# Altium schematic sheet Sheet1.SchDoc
size E
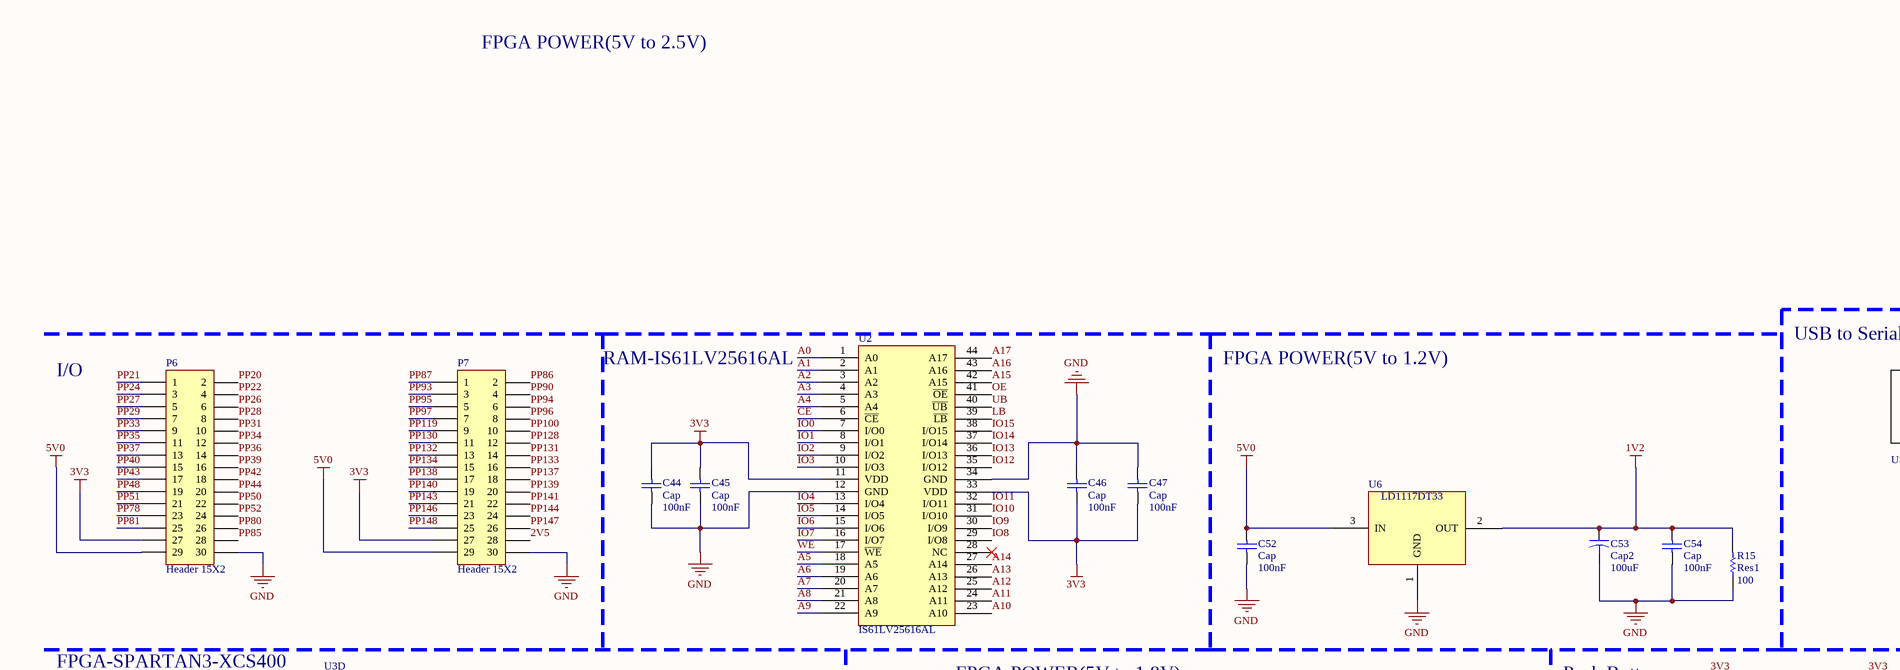
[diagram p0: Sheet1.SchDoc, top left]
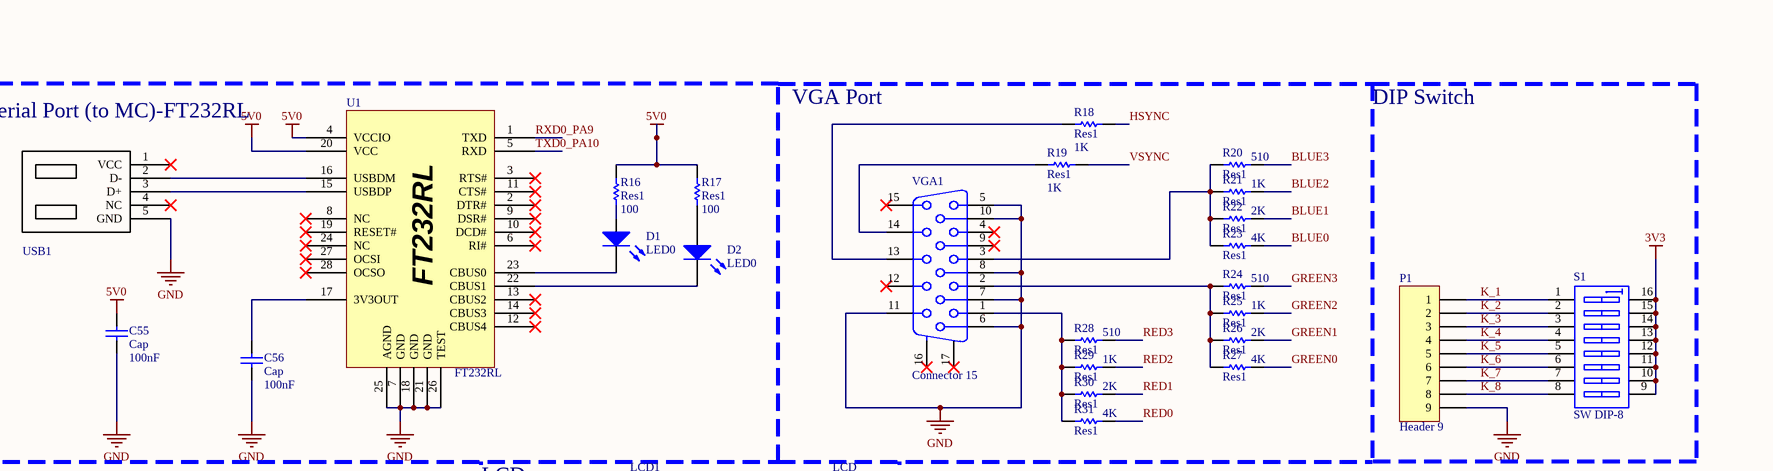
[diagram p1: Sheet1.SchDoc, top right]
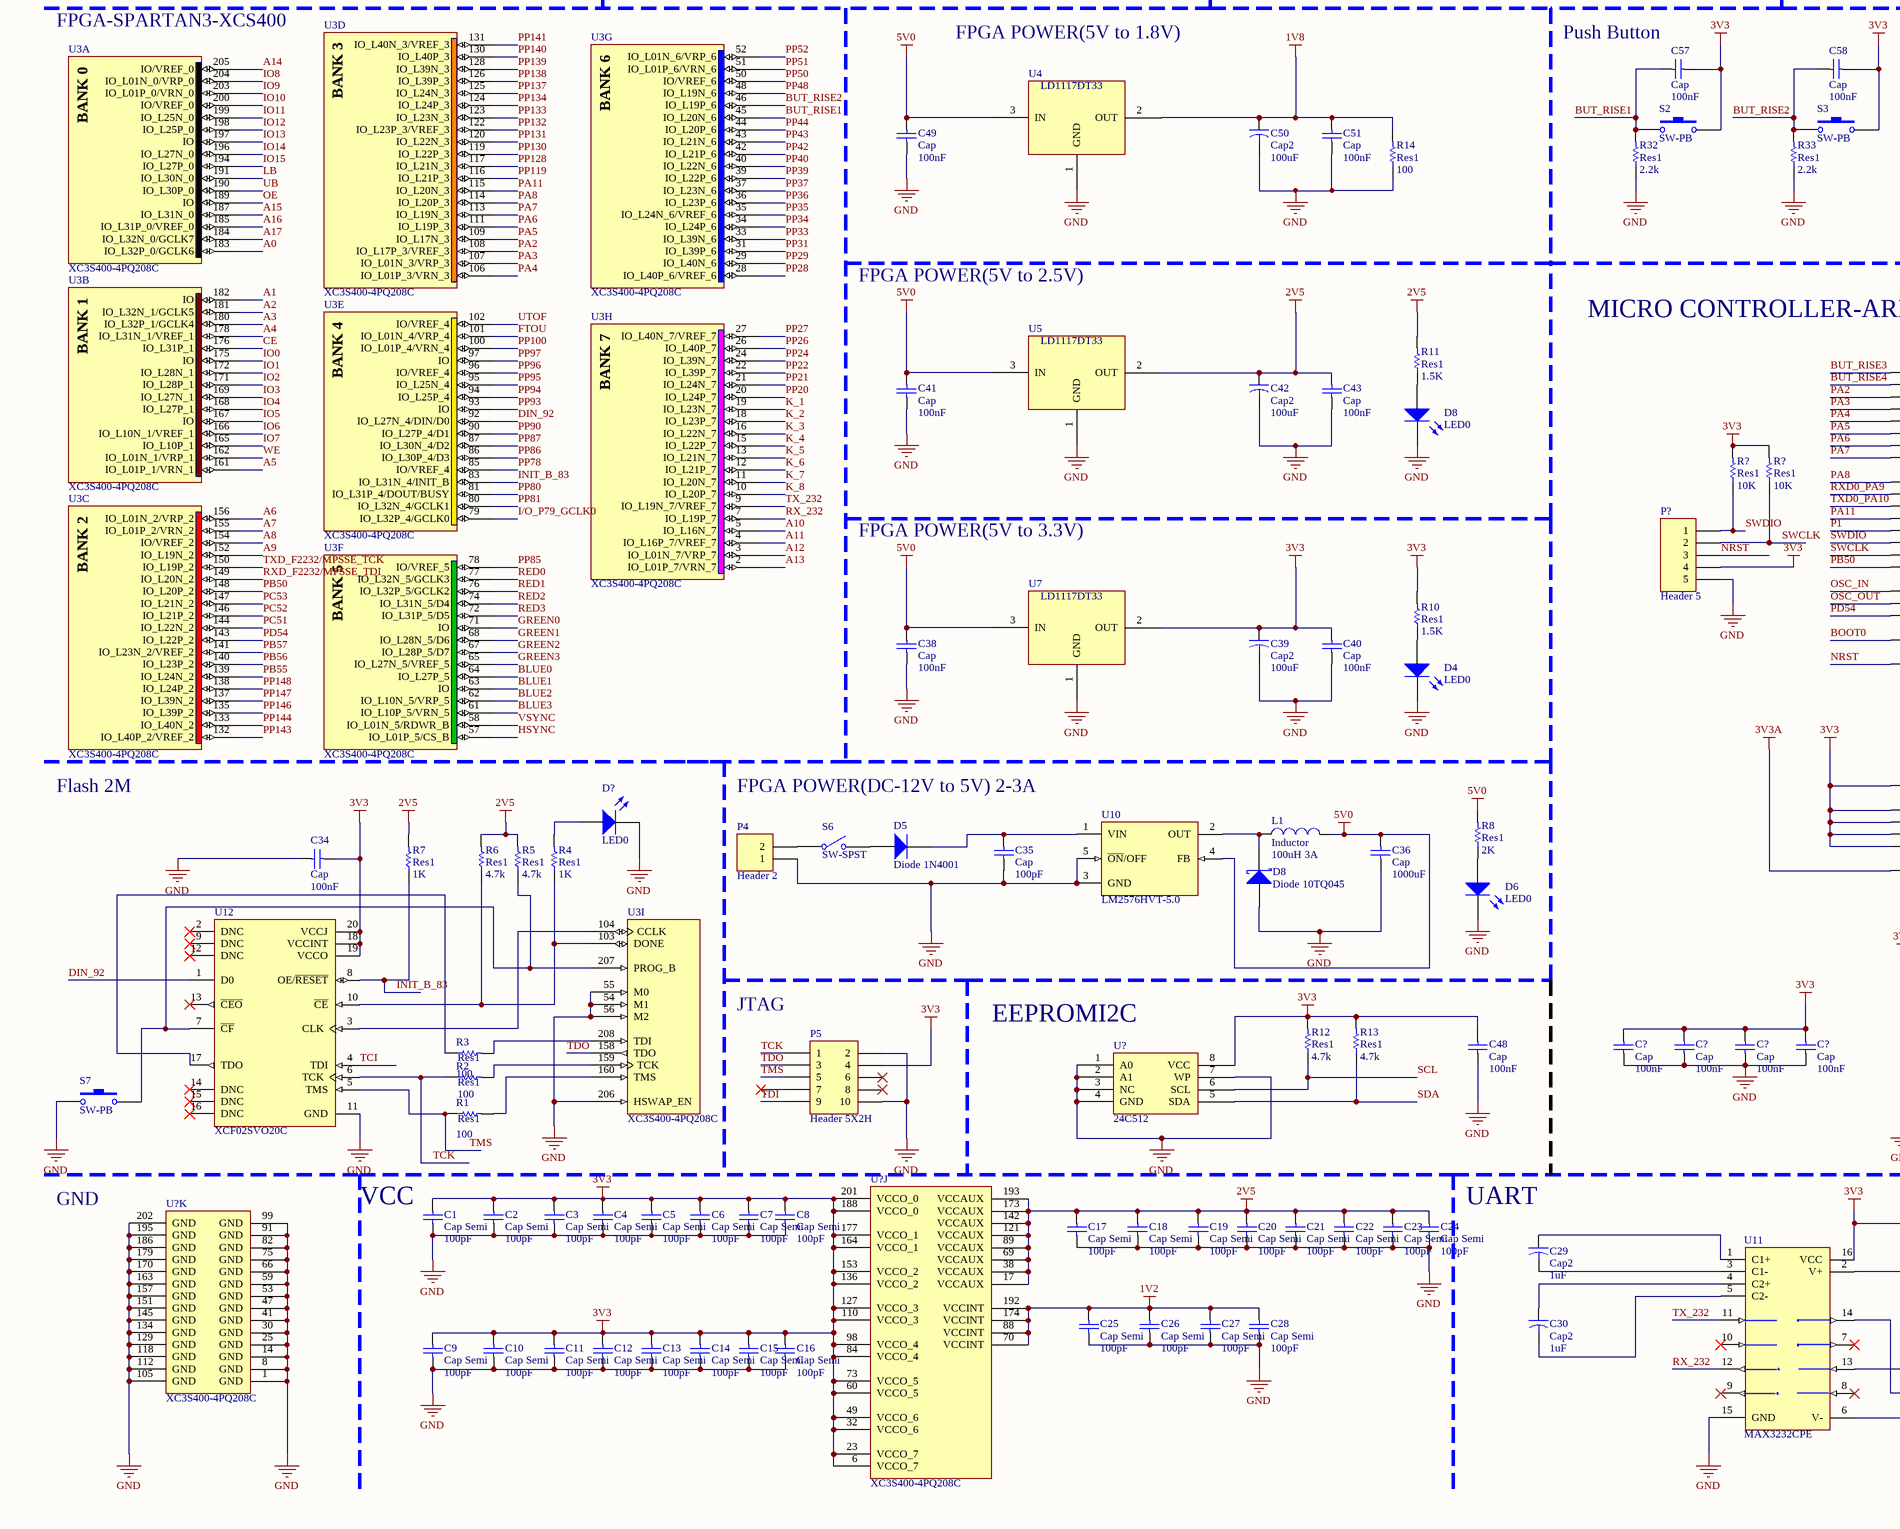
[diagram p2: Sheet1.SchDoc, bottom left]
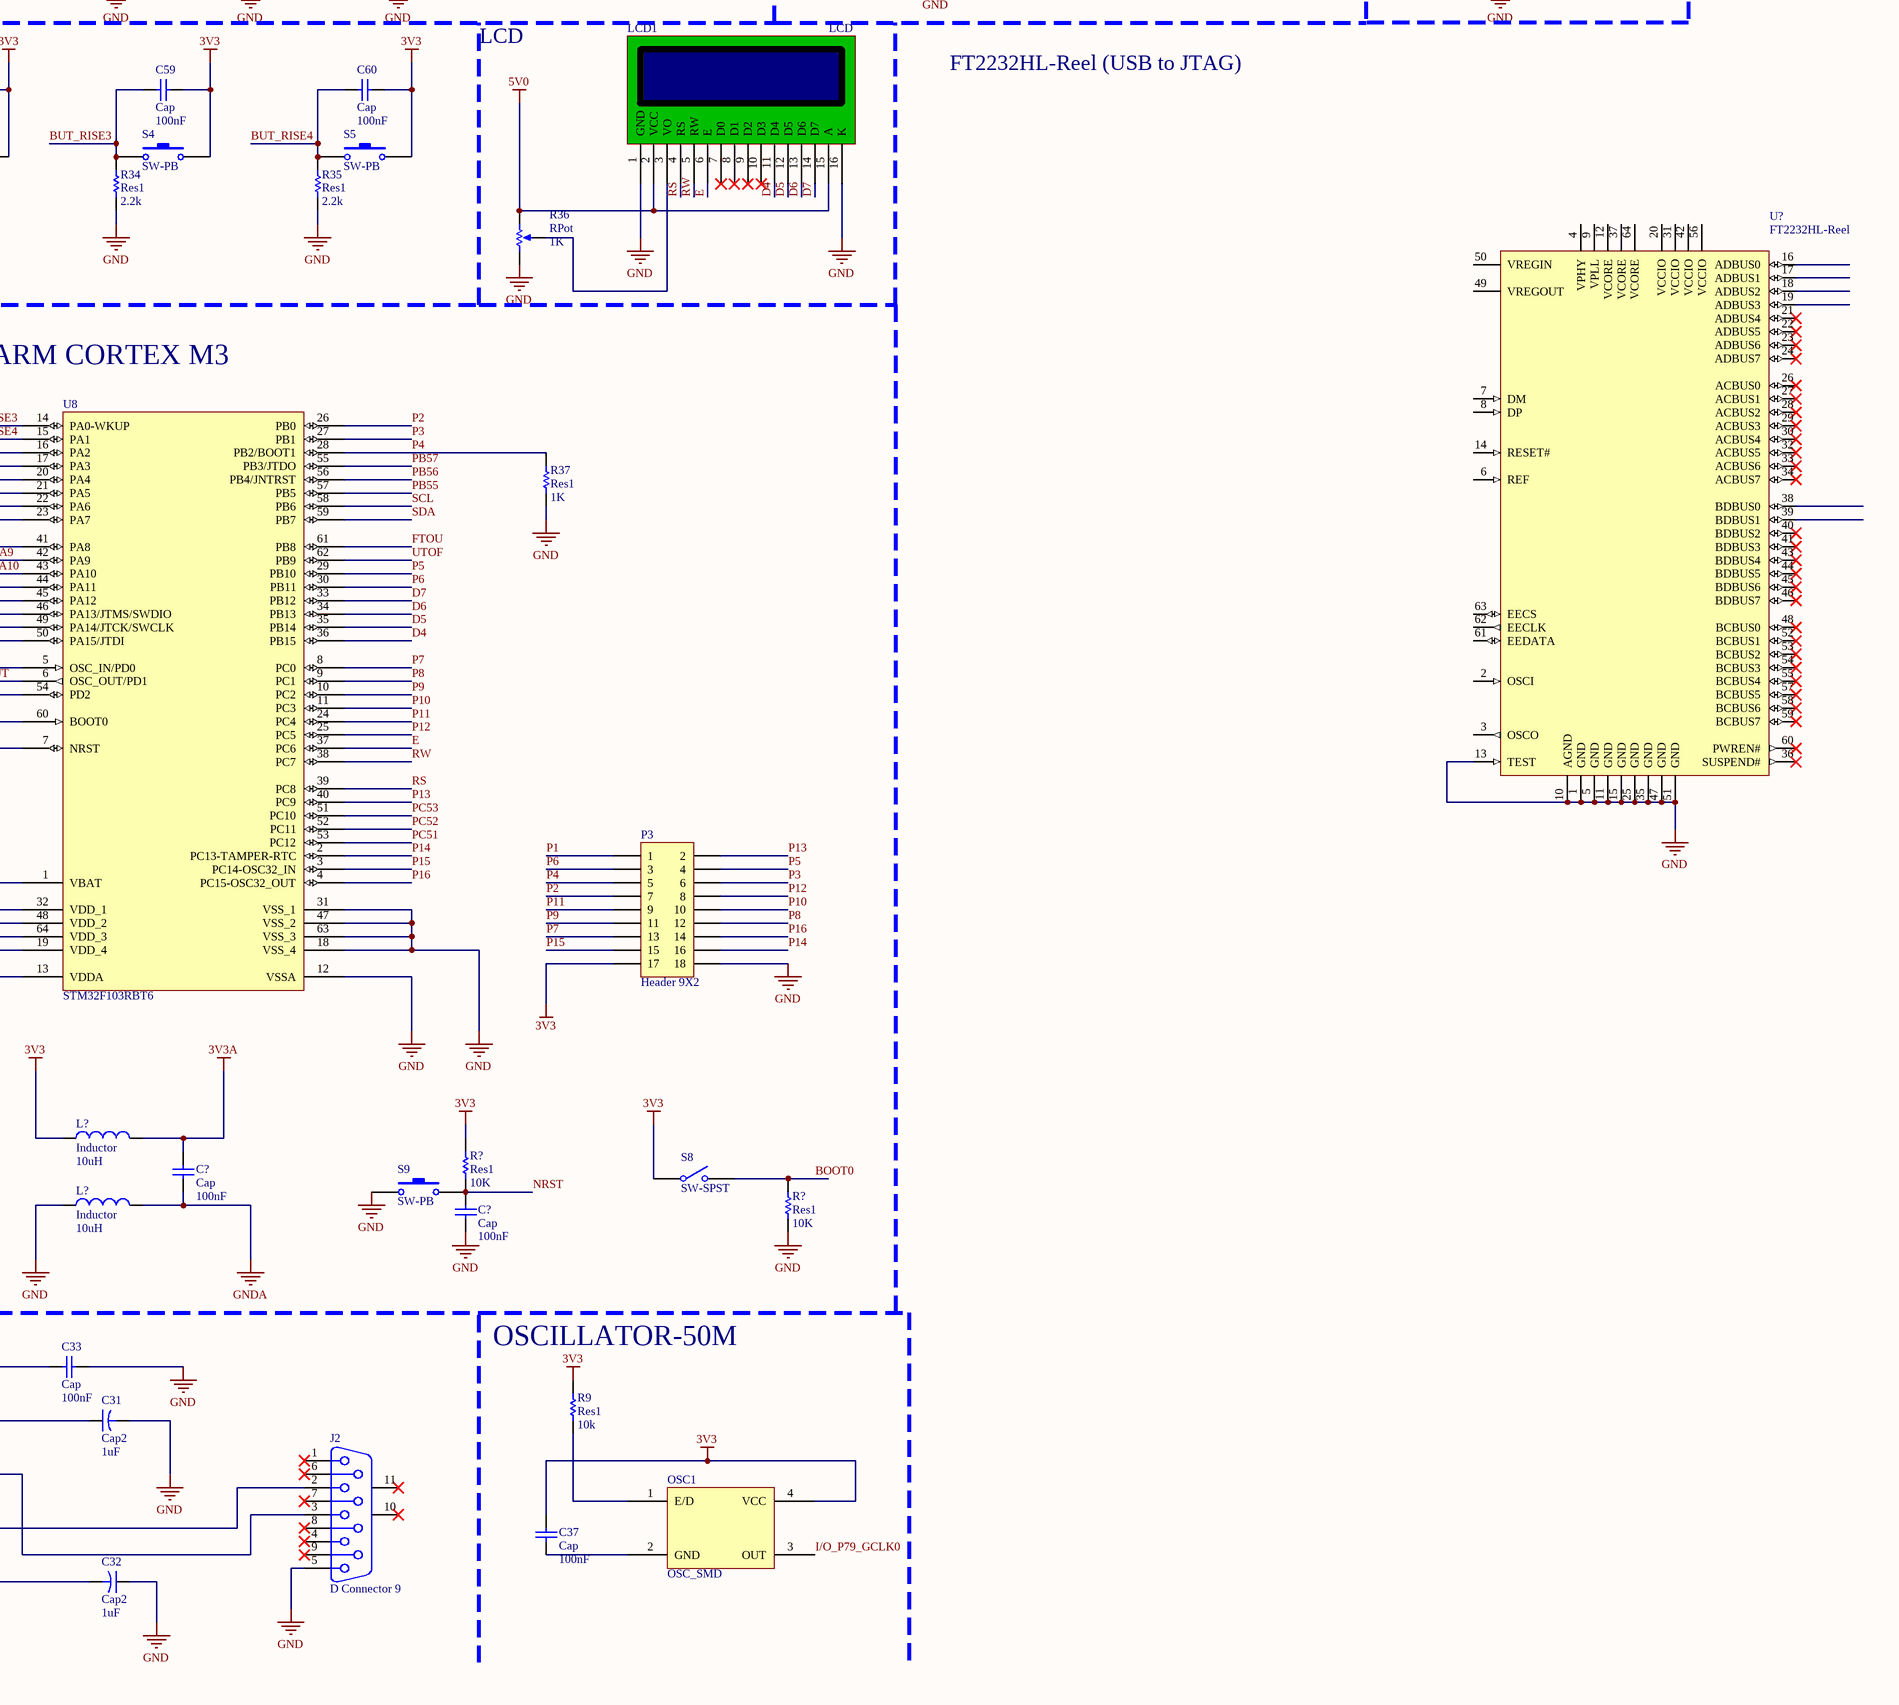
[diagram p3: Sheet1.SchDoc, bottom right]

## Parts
(Parts that share a designator on the sheet are numbered #1, #2 ... from top to bottom, then left to right.)
C1  Cap Semi  value 100pF  [C1206]
C2  Cap Semi  value 100pF  [C1206]
C3  Cap Semi  value 100pF  [C1206]
C4  Cap Semi  value 100pF  [C1206]
C5  Cap Semi  value 100pF  [C1206]
C6  Cap Semi  value 100pF  [C1206]
C7  Cap Semi  value 100pF  [C1206]
C8  Cap Semi  value 100pF  [C1206]
C9  Cap Semi  value 100pF  [C1206]
C10  Cap Semi  value 100pF  [C1206]
C11  Cap Semi  value 100pF  [C1206]
C12  Cap Semi  value 100pF  [C1206]
C13  Cap Semi  value 100pF  [C1206]
C14  Cap Semi  value 100pF  [C1206]
C15  Cap Semi  value 100pF  [C1206]
C16  Cap Semi  value 100pF  [C1206]
C17  Cap Semi  value 100pF  [C1206]
C18  Cap Semi  value 100pF  [C1206]
C19  Cap Semi  value 100pF  [C1206]
C20  Cap Semi  value 100pF  [C1206]
C21  Cap Semi  value 100pF  [C1206]
C22  Cap Semi  value 100pF  [C1206]
C23  Cap Semi  value 100pF  [C1206]
C24  Cap Semi  value 100pF  [C1206]
C25  Cap Semi  value 100pF  [C1206]
C26  Cap Semi  value 100pF  [C1206]
C27  Cap Semi  value 100pF  [C1206]
C28  Cap Semi  value 100pF  [C1206]
C29  Cap2  value 1uF  [CAPR5-4X5]
C30  Cap2  value 1uF  [CAPR5-4X5]
C31  Cap2  value 1uF  [CAPR5-4X5]
C32  Cap2  value 1uF  [CAPR5-4X5]
C33  Cap  value 100nF  [RAD-0.3]
C34  Cap  value 100nF  [RAD-0.3]
C35  Cap  value 100pF  [RAD-0.3]
C36  Cap  value 1000uF  [RAD-0.3]
C37  Cap  value 100nF  [RAD-0.3]
C38  Cap  value 100nF  [RAD-0.3]
C39  Cap2  value 100uF  [CAPR5-4X5]
C40  Cap  value 100nF  [RAD-0.3]
C41  Cap  value 100nF  [RAD-0.3]
C42  Cap2  value 100uF  [CAPR5-4X5]
C43  Cap  value 100nF  [RAD-0.3]
C44  Cap  value 100nF  [RAD-0.3]
C45  Cap  value 100nF  [RAD-0.3]
C46  Cap  value 100nF  [RAD-0.3]
C47  Cap  value 100nF  [RAD-0.3]
C48  Cap  value 100nF  [RAD-0.3]
C49  Cap  value 100nF  [RAD-0.3]
C50  Cap2  value 100uF  [CAPR5-4X5]
C51  Cap  value 100nF  [RAD-0.3]
C52  Cap  value 100nF  [RAD-0.3]
C53  Cap2  value 100uF  [CAPR5-4X5]
C54  Cap  value 100nF  [RAD-0.3]
C55  Cap  value 100nF  [RAD-0.3]
C56  Cap  value 100nF  [RAD-0.3]
C57  Cap  value 100nF  [RAD-0.3]
C58  Cap  value 100nF  [RAD-0.3]
C59  Cap  value 100nF  [RAD-0.3]
C60  Cap  value 100nF  [RAD-0.3]
C?#1  Cap  value 100nF  [RAD-0.3]
C?#2  Cap  value 100nF  [RAD-0.3]
C?#3  Cap  value 100nF  [RAD-0.3]
C?#4  Cap  value 100nF  [RAD-0.3]
C?#5  Cap  value 100nF  [RAD-0.3]
C?#6  Cap  value 100nF  [RAD-0.3]
D1  LED0  [LED-0]
D2  LED0  [LED-0]
D4  LED0  [LED-0]
D5  Diode 1N4001  [DO-41]
D6  LED0  [LED-0]
D8#1  LED0  [LED-0]
D8#2  Diode 10TQ045  [TO-220AC]
D?  LED0  [LED-0]
J2  D Connector 9  [DSUB1.385-2H9]
L1  Inductor  value 100uH 3A  [0402-A]
L?#1  Inductor  value 10uH  [0402-A]
L?#2  Inductor  value 10uH  [0402-A]
LCD1  LCD  [LCD2x16_3d]
OSC1  OSC_SMD  [OSC_SMD]
P1  Header 9  [HDR1X9]
P3  Header 9X2  [HDR2X9]
P4  Header 2  [HDR1X2]
P5  Header 5X2H  [HDR2X5H]
P6  Header 15X2  [HDR2X15]
P7  Header 15X2  [HDR2X15]
P?  Header 5  [HDR1X5]
R1  Res1  value 100  [AXIAL-0.3]
R2  Res1  value 100  [AXIAL-0.3]
R3  Res1  value 100  [AXIAL-0.3]
R4  Res1  value 1K  [AXIAL-0.3]
R5  Res1  value 4.7k  [AXIAL-0.3]
R6  Res1  value 4.7k  [AXIAL-0.3]
R7  Res1  value 1K  [AXIAL-0.3]
R8  Res1  value 2K  [AXIAL-0.3]
R9  Res1  value 10k  [AXIAL-0.3]
R10  Res1  value 1.5K  [AXIAL-0.3]
R11  Res1  value 1.5K  [AXIAL-0.3]
R12  Res1  value 4.7k  [AXIAL-0.3]
R13  Res1  value 4.7k  [AXIAL-0.3]
R14  Res1  value 100  [AXIAL-0.3]
R15  Res1  value 100  [AXIAL-0.3]
R16  Res1  value 100  [AXIAL-0.3]
R17  Res1  value 100  [AXIAL-0.3]
R18  Res1  value 1K  [AXIAL-0.3]
R19  Res1  value 1K  [AXIAL-0.3]
R20  Res1  value 510  [AXIAL-0.3]
R21  Res1  value 1K  [AXIAL-0.3]
R22  Res1  value 2K  [AXIAL-0.3]
R23  Res1  value 4K  [AXIAL-0.3]
R24  Res1  value 510  [AXIAL-0.3]
R25  Res1  value 1K  [AXIAL-0.3]
R26  Res1  value 2K  [AXIAL-0.3]
R27  Res1  value 4K  [AXIAL-0.3]
R28  Res1  value 510  [AXIAL-0.3]
R29  Res1  value 1K  [AXIAL-0.3]
R30  Res1  value 2K  [AXIAL-0.3]
R31  Res1  value 4K  [AXIAL-0.3]
R32  Res1  value 2.2k  [AXIAL-0.3]
R33  Res1  value 2.2k  [AXIAL-0.3]
R34  Res1  value 2.2k  [AXIAL-0.3]
R35  Res1  value 2.2k  [AXIAL-0.3]
R36  RPot  value 1K  [VR5]
R37  Res1  value 1K  [AXIAL-0.3]
R?#1  Res1  value 10K  [AXIAL-0.3]
R?#2  Res1  value 10K  [AXIAL-0.3]
R?#3  Res1  value 10K  [AXIAL-0.3]
R?#4  Res1  value 10K  [AXIAL-0.3]
S1  SW DIP-8  [DIP_SW_8WAY_SMD]
S2  SW-PB  [SPST-2]
S3  SW-PB  [SPST-2]
S4  SW-PB  [SPST-2]
S5  SW-PB  [SPST-2]
S6  SW-SPST  [SPST-2]
S7  SW-PB  [SPST-2]
S8  SW-SPST  [SPST-2]
S9  SW-PB  [SPST-2]
U1  FT232RL  [SOP28]
U2  IS61LV25616AL  [SOP44]
U3  XC3S400-4PQ208C  [PQ208_N]  (parts A,B,C,D,E,F,G,H,I of 11)
U4  LD1117DT33  [SOT223]
U5  LD1117DT33  [SOT223]
U6  LD1117DT33  [SOT223]
U7  LD1117DT33  [SOT223]
U8  STM32F103RBT6  [LQFP64_N]
U10  LM2576HVT-5.0  [T05A]
U11  MAX3232CPE  [PE16]
U12  XCF02SVO20C  [VO20_N]
U?#1  FT2232HL-Reel  [PCBComponent_1]
U?#2  24C512  [SOP8]
U?#3  XC3S400-4PQ208C  [PQ208_N]  (part J of 11)
U?#4  XC3S400-4PQ208C  [PQ208_N]  (part K of 11)
USB1  MICRO_USB  [MINI_USB_NEW]  (value not drawn)
VGA1  Connector 15  [050DSUB0.762-4H15]

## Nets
1V2: C25.2 C26.2 C27.2 C28.2 C53.1 C54.2 R15.2 U6.2(OUT) U?#3.70(VCCINT) U?#3.88(VCCINT) U?#3.174(VCCINT) U?#3.192(VCCINT)
1V8: C50.1 C51.2 R14.2 U4.2(OUT)
2V5: C17.2 C18.2 C19.2 C20.2 C21.2 C22.2 C23.2 C24.2 C42.1 C43.2 P7.28 R5.2 R6.2 R7.2 R11.2 U5.2(OUT) U?#3.17(VCCAUX) U?#3.38(VCCAUX) U?#3.69(VCCAUX) U?#3.89(VCCAUX) U?#3.121(VCCAUX) U?#3.142(VCCAUX) U?#3.173(VCCAUX) U?#3.193(VCCAUX)
3V3: C1.2 C2.2 C3.2 C4.2 C5.2 C6.2 C7.2 C8.2 C9.2 C10.2 C11.2 C12.2 C13.2 C14.2 C15.2 C16.2 C33.1 C34.2 C37.2 C39.1 C40.2 C44.2 C45.2 C46.1 C47.1 C48.2 C57.2 C58.2 C59.2 C60.2 C?#1.2 C?#2.2 C?#3.2 C?#4.2 L?#1.1 OSC1.4(VCC) P3.17 P5.4 P6.27 P7.27 P?.4 R9.2 R10.2 R12.2 R13.2 R?#1.2 R?#2.2 R?#3.2 S1.9(B8) S1.10(B7) S1.11(B6) S1.12(B5) S1.13(B4) S1.14(B3) S1.15(B2) S1.16(B1) S2.2 S3.2 S4.2 S5.2 S8.1(COMMON) U2.11(VDD) U2.33(VDD) U7.2(OUT) U8.1(VBAT) U8.19(VDD_4) U8.32(VDD_1) U8.48(VDD_2) U8.64(VDD_3) U11.16(VCC) U12.18(VCCINT) U12.19(VCCO) U12.20(VCCJ) U?#2.8(VCC) U?#3.6(VCCO_7) U?#3.23(VCCO_7) U?#3.32(VCCO_6) U?#3.49(VCCO_6) U?#3.60(VCCO_5) U?#3.73(VCCO_5) U?#3.84(VCCO_4) U?#3.98(VCCO_4) U?#3.110(VCCO_3) U?#3.127(VCCO_3) U?#3.136(VCCO_2) U?#3.153(VCCO_2) U?#3.164(VCCO_1) U?#3.177(VCCO_1) U?#3.188(VCCO_0) U?#3.201(VCCO_0)
3V3A: C?#5.2 L?#1.2 U8.13(VDDA)
5V0: C36.2 C38.2 C41.2 C49.2 C52.2 C55.2 L1.2 LCD1.2(VCC) LCD1.15(A) P6.29 P7.29 R8.2 R16.2 R17.2 R36.2(BOT) U1.4(VCCIO) U1.20(VCC) U4.3(IN) U5.3(IN) U6.3(IN) U7.3(IN) U10.4(FB)
GND: C1.1 C2.1 C3.1 C4.1 C5.1 C6.1 C7.1 C8.1 C9.1 C10.1 C11.1 C12.1 C13.1 C14.1 C15.1 C16.1 C17.1 C18.1 C19.1 C20.1 C21.1 C22.1 C23.1 C24.1 C25.1 C26.1 C27.1 C28.1 C31.2 C32.1 C33.2 C34.1 C35.1 C36.1 C38.1 C39.2 C40.1 C41.1 C42.2 C43.1 C44.1 C45.1 C46.2 C47.2 C48.1 C49.1 C50.2 C51.1 C52.1 C53.2 C54.1 C55.1 C56.1 C?#1.1 C?#2.1 C?#3.1 C?#4.1 C?#6.1 D4.2(K) D6.2(K) D8#1.2(K) D8#2.3(A) D?.2(K) J2.5 L?#2.1 LCD1.1(GND) LCD1.16(K) P1.9 P3.18 P4.1 P5.2 P5.10 P6.30 P7.30 P?.5 R14.1 R15.1 R32.1 R33.1 R34.1 R35.1 R36.1(TOP) R37.1 R?#4.1 S7.1 S9.1 U1.7(GND) U1.18(GND) U1.21(GND) U1.25(AGND) U1.26(TEST) U2.12(GND) U2.34(GND) U3.54(M1) U3.55(M0) U3.56(M2) U3.206(HSWAP_EN) U4.1(GND) U5.1(GND) U6.1(GND) U7.1(GND) U8.12(VSSA) U8.18(VSS_4) U8.31(VSS_1) U8.47(VSS_2) U8.63(VSS_3) U10.3(GND) U10.5(~{ON}/OFF) U11.15(GND) U12.11(GND) U?#1.1(GND) U?#1.5(GND) U?#1.10(AGND) U?#1.11(GND) U?#1.13(TEST) U?#1.15(GND) U?#1.25(GND) U?#1.35(GND) U?#1.47(GND) U?#1.51(GND) U?#2.1(A0) U?#2.2(A1) U?#2.3(NC) U?#2.4(GND) U?#2.7(WP) U?#4.1(GND) U?#4.8(GND) U?#4.14(GND) U?#4.25(GND) U?#4.30(GND) U?#4.41(GND) U?#4.47(GND) U?#4.53(GND) U?#4.59(GND) U?#4.66(GND) U?#4.75(GND) U?#4.82(GND) U?#4.91(GND) U?#4.99(GND) U?#4.105(GND) U?#4.112(GND) U?#4.118(GND) U?#4.129(GND) U?#4.134(GND) U?#4.145(GND) U?#4.151(GND) U?#4.157(GND) U?#4.163(GND) U?#4.170(GND) U?#4.179(GND) U?#4.186(GND) U?#4.195(GND) U?#4.202(GND) USB1.5(GND) VGA1.5 VGA1.6 VGA1.7 VGA1.8 VGA1.10 VGA1.11
GNDA: C?#5.1 L?#2.2
A0: U2.1(A0) U3.183(IO_L32P_0/GCLK6)
A1: U2.2(A1) U3.182(IO)
A2: U2.3(A2) U3.181(IO_L32N_1/GCLK5)
A3: U2.4(A3) U3.180(IO_L32P_1/GCLK4)
A4: U2.5(A4) U3.178(IO_L31N_1/VREF_1)
A5: U2.18(A5) U3.161(IO_L01P_1/VRN_1)
A6: U2.19(A6) U3.156(IO_L01N_2/VRP_2)
A7: U2.20(A7) U3.155(IO_L01P_2/VRN_2)
A8: U2.21(A8) U3.154(IO/VREF_2)
A9: U2.22(A9) U3.152(IO_L19N_2)
A10: U2.23(A10) U3.5(IO_L16N_7)
A11: U2.24(A11) U3.4(IO_L16P_7/VREF_7)
A12: U2.25(A12) U3.3(IO_L01N_7/VRP_7)
A13: U2.26(A13) U3.2(IO_L01P_7/VRN_7)
A14: U2.27(A14) U3.205(IO/VREF_0)
A15: U2.42(A15) U3.187(IO_L31N_0)
A16: U2.43(A16) U3.185(IO_L31P_0/VREF_0)
A17: U2.44(A17) U3.184(IO_L32N_0/GCLK7)
BLUE0: R23.2 U3.64(IO_L27P_5)
BLUE1: R22.2 U3.63(IO)
BLUE2: R21.2 U3.62(IO_L10N_5/VRP_5)
BLUE3: R20.2 U3.61(IO_L10P_5/VRN_5)
BOOT0: R?#4.2 S8.2(NO) U8.60(BOOT0)
BUT_RISE1: C57.1 R32.2 S2.1 U3.45(IO_L20N_6)
BUT_RISE2: C58.1 R33.2 S3.1 U3.46(IO_L19P_6)
BUT_RISE3: C59.1 R34.2 S4.1 U8.14(PA0-WKUP)
BUT_RISE4: C60.1 R35.2 S5.1 U8.15(PA1)
CE: U2.6(~{CE}) U3.176(IO_L31P_1)
D4: LCD1.11(D4) U8.36(PB15)
D5: LCD1.12(D5) U8.35(PB14)
D6: LCD1.13(D6) U8.34(PB13)
D7: LCD1.14(D7) U8.33(PB12)
DIN_92: U3.92(IO_L27N_4/DIN/D0) U12.1(D0)
E: LCD1.6(E) U8.37(PC6)
FTOU: U3.101(IO_L01N_4/VRP_4) U8.61(PB8)
GREEN0: R27.2 U3.71(IO)
GREEN1: R26.2 U3.68(IO_L28N_5/D6)
GREEN2: R25.2 U3.67(IO_L28P_5/D7)
GREEN3: R24.2 U3.65(IO_L27N_5/VREF_5)
HSYNC: R18.2 U3.57(IO_L01P_5/CS_B)
I/O_P79_GCLK0: OSC1.3(OUT) U3.79(IO_L32P_4/GCLK0)
INIT_B_83: R7.1 U3.83(IO_L31N_4/INIT_B) U12.8(OE/~{RESET})
IO0: U2.7(I/O0) U3.175(IO)
IO1: U2.8(I/O1) U3.172(IO_L28N_1)
IO2: U2.9(I/O2) U3.171(IO_L28P_1)
IO3: U2.10(I/O3) U3.169(IO_L27N_1)
IO4: U2.13(I/O4) U3.168(IO_L27P_1)
IO5: U2.14(I/O5) U3.167(IO)
IO6: U2.15(I/O6) U3.166(IO_L10N_1/VREF_1)
IO7: U2.16(I/O7) U3.165(IO_L10P_1)
IO8: U2.29(I/O8) U3.204(IO_L01N_0/VRP_0)
IO9: U2.30(I/O9) U3.203(IO_L01P_0/VRN_0)
IO10: U2.31(I/O10) U3.200(IO/VREF_0)
IO11: U2.32(I/O11) U3.199(IO_L25N_0)
IO12: U2.35(I/O12) U3.198(IO_L25P_0)
IO13: U2.36(I/O13) U3.197(IO)
IO14: U2.37(I/O14) U3.196(IO_L27N_0)
IO15: U2.38(I/O15) U3.194(IO_L27P_0)
K_1: P1.1 S1.1(A1) U3.19(IO_L23N_7)
K_2: P1.2 S1.2(A2) U3.18(IO_L23P_7)
K_3: P1.3 S1.3(A3) U3.16(IO_L22N_7)
K_4: P1.4 S1.4(A4) U3.15(IO_L22P_7)
K_5: P1.5 S1.5(A5) U3.13(IO_L21N_7)
K_6: P1.6 S1.6(A6) U3.12(IO_L21P_7)
K_7: P1.7 S1.7(A7) U3.11(IO_L20N_7)
K_8: P1.8 S1.8(A8) U3.10(IO_L20P_7)
LB: U2.39(~{LB}) U3.191(IO_L30N_0)
NRST: C?#6.2 P?.3 R?#3.1 S9.2 U8.7(NRST)
OE: U2.41(~{OE}) U3.189(IO)
OSC_IN: U8.5(OSC_IN/PD0)
OSC_OUT: U8.6(OSC_OUT/PD1)
P1: P3.1 U8.45(PA12)
P2: P3.7 U8.26(PB0)
P3: P3.6 U8.27(PB1)
P4: P3.5 R37.2 U8.28(PB2/BOOT1)
P5: P3.4 U8.29(PB10)
P6: P3.3 U8.30(PB11)
P7: P3.13 U8.8(PC0)
P8: P3.12 U8.9(PC1)
P9: P3.11 U8.10(PC2)
P10: P3.10 U8.11(PC3)
P11: P3.9 U8.24(PC4)
P12: P3.8 U8.25(PC5)
P13: P3.2 U8.40(PC9)
P14: P3.16 U8.2(PC13-TAMPER-RTC)
P15: P3.15 U8.3(PC14-OSC32_IN)
P16: P3.14 U8.4(PC15-OSC32_OUT)
PA2: U3.108(IO_L17P_3/VREF_3) U8.16(PA2)
PA3: U3.107(IO_L01N_3/VRP_3) U8.17(PA3)
PA4: U3.106(IO_L01P_3/VRN_3) U8.20(PA4)
PA5: U3.109(IO_L17N_3) U8.21(PA5)
PA6: U3.111(IO_L19P_3) U8.22(PA6)
PA7: U3.113(IO_L19N_3) U8.23(PA7)
PA8: U3.114(IO_L20P_3) U8.41(PA8)
PA11: U3.115(IO_L20N_3) U8.44(PA11)
PB50: U3.148(IO_L20P_2) U8.50(PA15/JTDI)
PB55: U3.139(IO_L24N_2) U8.57(PB5)
PB56: U3.140(IO_L23P_2) U8.56(PB4/JNTRST)
PB57: U3.141(IO_L23N_2/VREF_2) U8.55(PB3/JTDO)
PC51: U3.144(IO_L22N_2) U8.53(PC12)
PC52: U3.146(IO_L21P_2) U8.52(PC11)
PC53: U3.147(IO_L21N_2) U8.51(PC10)
PD54: U3.143(IO_L22P_2) U8.54(PD2)
PP20: P6.2 U3.20(IO_L24P_7)
PP21: P6.1 U3.21(IO_L24N_7)
PP22: P6.4 U3.22(IO_L39P_7)
PP24: P6.3 U3.24(IO_L39N_7)
PP26: P6.6 U3.26(IO_L40P_7)
PP27: P6.5 U3.27(IO_L40N_7/VREF_7)
PP28: P6.8 U3.28(IO_L40P_6/VREF_6)
PP29: P6.7 U3.29(IO_L40N_6)
PP31: P6.10 U3.31(IO_L39P_6)
PP33: P6.9 U3.33(IO_L39N_6)
PP34: P6.12 U3.34(IO_L24P_6)
PP35: P6.11 U3.35(IO_L24N_6/VREF_6)
PP36: P6.14 U3.36(IO_L23P_6)
PP37: P6.13 U3.37(IO_L23N_6)
PP39: P6.16 U3.39(IO_L22P_6)
PP40: P6.15 U3.40(IO_L22N_6)
PP42: P6.18 U3.42(IO_L21P_6)
PP43: P6.17 U3.43(IO_L21N_6)
PP44: P6.20 U3.44(IO_L20P_6)
PP48: P6.19 U3.48(IO_L19N_6)
PP50: P6.22 U3.50(IO/VREF_6)
PP51: P6.21 U3.51(IO_L01P_6/VRN_6)
PP52: P6.24 U3.52(IO_L01N_6/VRP_6)
PP78: P6.23 U3.85(IO/VREF_4)
PP80: P6.26 U3.81(IO_L31P_4/DOUT/BUSY)
PP81: P6.25 U3.80(IO_L32N_4/GCLK1)
PP85: P6.28 U3.78(IO/VREF_5)
PP86: P7.2 U3.86(IO_L30P_4/D3)
PP87: P7.1 U3.87(IO_L30N_4/D2)
PP90: P7.4 U3.90(IO_L27P_4/D1)
PP93: P7.3 U3.93(IO)
PP94: P7.6 U3.94(IO_L25P_4)
PP95: P7.5 U3.95(IO_L25N_4)
PP96: P7.8 U3.96(IO/VREF_4)
PP97: P7.7 U3.97(IO)
PP100: P7.10 U3.100(IO_L01P_4/VRN_4)
PP119: P7.9 U3.116(IO_L21P_3)
PP128: P7.12 U3.117(IO_L21N_3)
PP130: P7.11 U3.119(IO_L22P_3)
PP131: P7.14 U3.120(IO_L22N_3)
PP132: P7.13 U3.122(IO_L23P_3/VREF_3)
PP133: P7.16 U3.123(IO_L23N_3)
PP134: P7.15 U3.124(IO_L24P_3)
PP137: P7.18 U3.125(IO_L24N_3)
PP138: P7.17 U3.126(IO_L39P_3)
PP139: P7.20 U3.128(IO_L39N_3)
PP140: P7.19 U3.130(IO_L40P_3)
PP141: P7.22 U3.131(IO_L40N_3/VREF_3)
PP143: P7.21 U3.132(IO_L40P_2/VREF_2)
PP144: P7.24 U3.133(IO_L40N_2)
PP146: P7.23 U3.135(IO_L39P_2)
PP147: P7.26 U3.137(IO_L39N_2)
PP148: P7.25 U3.138(IO_L24P_2)
RED0: R31.2 U3.77(IO_L32N_5/GCLK3)
RED1: R30.2 U3.76(IO_L32P_5/GCLK2)
RED2: R29.2 U3.74(IO_L31N_5/D4)
RED3: R28.2 U3.72(IO_L31P_5/D5)
RS: LCD1.4(RS) U8.39(PC8)
RW: LCD1.5(RW) U8.38(PC7)
RX_232: U3.7(IO_L19P_7) U11.12(R1OUT)
RXD0_PA9: U1.1(TXD) U8.42(PA9)
RXD_F2232/MPSSE_TDI: U3.149(IO_L20N_2)
SCL: R12.1 U8.58(PB6) U?#2.6(SCL)
SDA: R13.1 U8.59(PB7) U?#2.5(SDA)
SWCLK: P?.2 R?#2.1 U8.49(PA14/JTCK/SWCLK)
SWDIO: P?.1 R?#1.1 U8.46(PA13/JTMS/SWDIO)
TCI: U12.4(TDI)
TCK: P5.1 R2.1 U12.6(TCK)
TDI: P5.9
TDO: P5.3 U3.158(TDO)
TMS: P5.5 R1.1 U12.5(TMS)
TX_232: U3.9(IO_L19N_7/VREF_7) U11.11(T1IN)
TXD0_PA10: U1.5(RXD) U8.43(PA10)
TXD_F2232/MPSSE_TCK: U3.150(IO_L19P_2)
UB: U2.40(~{UB}) U3.190(IO_L30P_0)
UTOF: U3.102(IO/VREF_4) U8.62(PB9)
VSYNC: R19.2 U3.58(IO_L01N_5/RDWR_B)
WE: U2.17(~{WE}) U3.162(IO_L01N_1/VRP_1)
NetC29_1: C29.1 U11.1(C1+)
NetC29_2: C29.2 U11.3(C1-)
NetC30_1: C30.1 U11.4(C2+)
NetC30_2: C30.2 U11.5(C2-)
NetC31_1: C31.1 U11.2(V+)
NetC32_2: C32.2 U11.6(V-)
NetC35_2: C35.2 D5.2(K) U10.1(VIN)
NetC37_1: C37.1 OSC1.2(GND)
NetC56_2: C56.2 U1.17(3V3OUT)
NetD1_1: D1.1(A) R16.1
NetD1_2: D1.2(K) U1.23(CBUS0)
NetD2_1: D2.1(A) R17.1
NetD2_2: D2.2(K) U1.22(CBUS1)
NetD4_1: D4.1(A) R10.1
NetD5_1: D5.1(A) S6.2(NO)
NetD6_1: D6.1(A) R8.1
NetD8#1_1: D8#1.1(A) R11.1
NetD8#2_1: D8#2.1(K) L1.1 U10.2(OUT)
NetD?_1: D?.1(A) R4.2
NetJ2_2: J2.2 U11.13(R1IN)
NetJ2_3: J2.3 U11.14(T1OUT)
NetLCD1_3: LCD1.3(VO) R36.3(TAP)
NetOSC1_1: OSC1.1(E/D) R9.1
NetP4_2: P4.2 S6.1(COMMON)
NetR1_2: R1.2 U3.160(TMS)
NetR2_2: R2.2 U3.159(TCK)
NetR3_1: R3.1 U12.17(TDO)
NetR3_2: R3.2 U3.208(TDI)
NetR4_1: R4.1 R6.1 U3.103(DONE) U12.10(~{CE})
NetR5_1: R5.1 S7.2 U3.207(PROG_B) U12.7(~{CF})
NetR18_1: R18.1 VGA1.13
NetR19_1: R19.1 VGA1.14
NetR20_1: R20.1 R21.1 R22.1 R23.1 VGA1.3
NetR24_1: R24.1 R25.1 R26.1 R27.1 VGA1.2
NetR28_1: R28.1 R29.1 R30.1 R31.1 VGA1.1
NetU1_15: U1.15(USBDP) USB1.3(D+)
NetU1_16: U1.16(USBDM) USB1.2(D-)
NetU3_104: U3.104(CCLK) U12.3(CLK)

Not connected (* = marked no-connect by the designer): J2 1* 4* 6* 7* 8* 9* 10(MH1)* 11(MH2)*; LCD1 7(D0)* 8(D1)* 9(D2)* 10(D3)*; P5 6* 7* 8*; U1 2(DTR#)* 3(RTS#)* 6(RI#)* 8(NC)* 9(DSR#)* 10(DCD#)* 11(CTS#)* 12(CBUS4)* 13(CBUS2)* 14(CBUS3)* 19(RESET#)* 24(NC)* 27(OCSI)* 28(OCSO)*; U2 28(NC)*; U11 7(T2OUT)* 8(R2IN)* 9(R2OUT)* 10(T2IN)*; U12 2(DNC)* 9(DNC)* 12(DNC)* 13(~{CEO})* 14(DNC)* 15(DNC)* 16(DNC)*; U?#1 2(OSCI) 3(OSCO) 4(VPHY) 6(REF) 7(DM) 8(DP) 9(VPLL) 12(VCORE) 14(RESET#) 16(ADBUS0) 17(ADBUS1) 18(ADBUS2) 19(ADBUS3) 20(VCCIO) 21(ADBUS4)* 22(ADBUS5)* 23(ADBUS6)* 24(ADBUS7)* 26(ACBUS0)* 27(ACBUS1)* 28(ACBUS2)* 29(ACBUS3)* 30(ACBUS4)* 31(VCCIO) 32(ACBUS5)* 33(ACBUS6)* 34(ACBUS7)* 36(SUSPEND#)* 37(VCORE) 38(BDBUS0) 39(BDBUS1) 40(BDBUS2)* 41(BDBUS3)* 42(VCCIO) 43(BDBUS4)* 44(BDBUS5)* 45(BDBUS6)* 46(BDBUS7)* 48(BCBUS0)* 49(VREGOUT) 50(VREGIN) 52(BCBUS1)* 53(BCBUS2)* 54(BCBUS3)* 55(BCBUS4)* 56(VCCIO) 57(BCBUS5)* 58(BCBUS6)* 59(BCBUS7)* 60(PWREN#)* 61(EEDATA) 62(EECLK) 63(EECS) 64(VCORE); USB1 1(VCC)* 4(NC)*; VGA1 4* 9* 12* 15* 16(MH1)* 17(MH2)*

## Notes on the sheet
- FPGA POWER(5V to 2.5V)
- I/O
- RAM-IS61LV25616AL
- FPGA POWER(5V to 1.2V)
- USB to Serial Port (to MC)-FT232RL
- VGA Port
- DIP Switch
- (near U3) FPGA-SPARTAN3-XCS400
- FPGA POWER(5V to 1.8V)
- (near C57) Push Button
- LCD
- FT2232HL-Reel (USB to JTAG)
- MICRO CONTROLLER-ARM CORTEX M3
- FPGA POWER(5V to 3.3V)
- Flash 2M
- FPGA POWER(DC-12V to 5V) 2-3A
- JTAG
- (near U?#2) EEPROMI2C
- GND
- (near C1) VCC
- UART
- (near R9) OSCILLATOR-50M

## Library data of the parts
C1-C28 = Cap Semi: Capacitor (Semiconductor SIM Model)
C29-C32 C39 C42 C50 C53 = Cap2: Capacitor
C33-C38 C40 C41 C43-C49 C51 C52 C54-C60 C?#1-C?#6 = Cap: Capacitor
D1 D2 D4 D6 D8#1 D? = LED0: Typical INFRARED GaAs LED
D5 = Diode 1N4001: 1 Amp General Purpose Rectifier
D8#2 = Diode 10TQ045: Schottky Rectifier; Note: Terminal 2 is the TAB and is electrically connected to the cathode
J2 = D Connector 9: Receptacle Assembly, 9 Position, Right Angle; PackageDocument: O; Positions: 9
L1 L?#1 L?#2 = Inductor: Code_IEC: 1005
OSC1 = Component_1: Designer:: Mohammad Ansari
P1 = Header 9: Header, 9-Pin
P3 = Header 9X2: Header, 9-Pin, Dual row
P4 = Header 2: Header, 2-Pin
P5 = Header 5X2H: Header, 5-Pin, Dual row, Right Angle
P6 P7 = Header 15X2: Header, 15-Pin, Dual row
P? = Header 5: Header, 5-Pin
R1-R35 R37 R?#1-R?#4 = Res1: Resistor
R36 = RPot: Potentiometer; Sim Note: Enter the Resistance value and the set point into parameter fields.; Set Position: 0.5
S1 = SW DIP-8: DIP Switch, 8 Position, SPST
S2-S5 S7 S9 = SW-PB: Switch
S6 S8 = SW-SPST: Single-Pole, Single-Throw Switch
U3 U?#3 U?#4 = XC3S400-4PQ208C: Spartan-3 1.2V FPGA, 141 User I/Os, 208-Pin PQFP, Standard Performance, Commercial Grade; Ordering Information: Additional code may have to be appended for different mask revision devices.
U4-U7 = Component_1
U8 = STM32F103RBT6: STM32 ARM-based 32-bit MCU with 128 Kbytes Flash, 64-pin LQFP, Industrial Temperature
U10 = LM2576HVT-5.0: SIMPLE SWITCHER; 3A Step-Down Voltage Regulator; Manufacturer: National Semiconductor; PackageTopMarking: NSUZXYTT*LM2576HVT*-5.0 P+; PowerWise: N
U11 = MAX3232CPE: 3.0V TO 5.5V, Low-Power, up to 1Mbps, True RS-232 Transceiver Using Four 0.1µF External Capacitor
U12 = XCF02SVO20C: XCF00S Series, Platform Flash In-System Programmable Configuration 3.3V PROM, 20-Pin TSOP, 2-Megabit, Commercial Grade
U?#1 = FT2232HL-Reel: Dual High Speed USB To Multipurpose UART/FIFO IC, 64-pin LQFP, Tape and Reel; Manufacturer: FTDI
VGA1 = Connector 15: Receptacle Assembly, 15-Pin, Sim Line Connector; PackageDocument: B; Positions: 15; Gender: Receptacle Header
